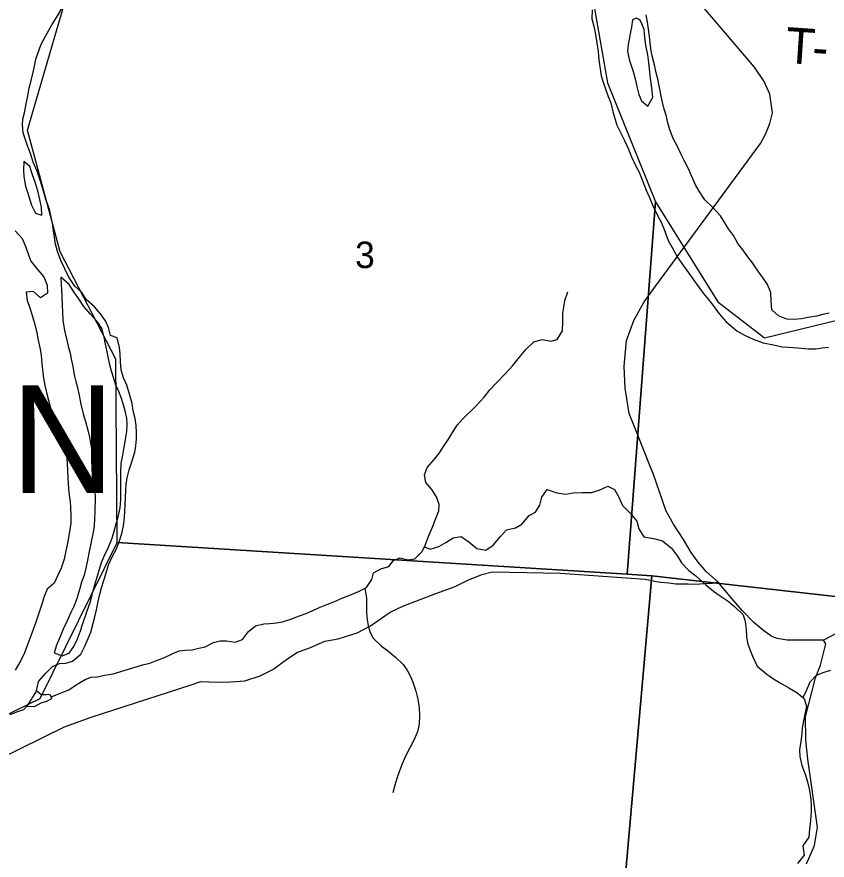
# Model space of a CAD drawing. Extents: x 0 to 34, y 0 to 22.
# Drawn here: x 26.095 to 27.377, y 16.768 to 18.103 of the extents above; entities that cross this region are included whole.
import ezdxf

# ---------------------------------------------------------------- set-up
doc = ezdxf.new("R2010")
doc.units = 0
for name, color, linetype in [('GM_X_County_Road', 7, 'Continuous'), ('GM_X_Major_River', 7, 'Continuous'), ('GM_X_Minor_River', 7, 'Continuous'), ('GM_X_Section', 7, 'Continuous'), ('GM_X_Section_Text', 7, 'Continuous'), ('GM_X_State_Route', 7, 'Continuous'), ('GM_X_Township_Road', 7, 'Continuous'), ('GM_X_Township_Road_Text', 7, 'Continuous'), ('GM_X_Township_Text', 7, 'Continuous')]:
    doc.layers.add(name, color=color, linetype=linetype)

msp = doc.modelspace()

# ---------------------------------------------------------------- linework, layer by layer
at = {"layer": 'GM_X_County_Road'}
for points in [[(26.066, 16.9284), (26.1704, 16.9793), (26.2127, 16.9945), (26.3706, 17.0458), (26.3861, 17.0514), (26.4111, 17.0501), (26.4335, 17.0507), (26.4558, 17.0521), (26.4801, 17.06), (26.4998, 17.0701), (26.5215, 17.0859), (26.5378, 17.0969), (26.5598, 17.1051), (26.5822, 17.1148), (26.6034, 17.1189), (26.6334, 17.1282), (26.6543, 17.1391), (26.6854, 17.161), (26.7059, 17.1703), (26.7332, 17.1808), (26.7579, 17.1902), (26.7882, 17.2014), (26.8084, 17.2115), (26.8304, 17.2205), (26.847, 17.225), (26.9549, 17.2225), (27.0893, 17.2131), (27.1068, 17.2096), (27.1135, 17.2083), (27.1266, 17.2073), (27.1376, 17.2058), (27.1441, 17.2058)], [(27.1441, 17.2058), (27.1462, 17.2058), (27.1572, 17.2056), (27.1676, 17.2053), (27.1757, 17.2056), (27.1888, 17.2066), (27.1952, 17.2068), (27.2039, 17.2091)]]:
    msp.add_lwpolyline(points, dxfattribs=at)
at = {"layer": 'GM_X_Major_River'}
msp.add_line((26.1259, 17.0362), (26.1106, 17.0119), dxfattribs=at)
for points in [[(26.2324, 17.2113), (26.2364, 17.2234), (26.2399, 17.2359), (26.2457, 17.2487), (26.2519, 17.26), (26.2569, 17.2725), (26.2612, 17.2853), (26.2636, 17.2978), (26.2653, 17.311), (26.2658, 17.3213), (26.2663, 17.3307), (26.2667, 17.3417), (26.2673, 17.3542), (26.2677, 17.3637), (26.2694, 17.3735), (26.2725, 17.3864), (26.2768, 17.3989), (26.2815, 17.414), (26.2831, 17.4242), (26.284, 17.4348), (26.2841, 17.445), (26.2835, 17.4564), (26.2821, 17.4674), (26.2792, 17.4796), (26.2774, 17.4914), (26.2734, 17.5058), (26.2687, 17.5203), (26.2635, 17.5317), (26.2598, 17.5443), (26.2589, 17.5579), (26.2582, 17.5701), (26.2572, 17.5799), (26.2536, 17.5951), (26.243, 17.599), (26.2401, 17.6116), (26.2353, 17.6223), (26.2275, 17.6333), (26.2178, 17.6441), (26.2047, 17.656), (26.198, 17.6667), (26.1867, 17.677), (26.1774, 17.6912), (26.1708, 17.7045), (26.1649, 17.7163), (26.1597, 17.73), (26.1561, 17.7437), (26.1543, 17.7544), (26.1529, 17.7646), (26.1511, 17.7768), (26.149, 17.7863), (26.1464, 17.7988), (26.1409, 17.814), (26.138, 17.8239), (26.1351, 17.8349), (26.1318, 17.8448), (26.127, 17.8589), (26.1208, 17.8734), (26.1164, 17.8871), (26.1116, 17.8989), (26.105, 17.9195), (26.104, 17.932), (26.1045, 17.9414), (26.1072, 17.9513), (26.1097, 17.9657), (26.1124, 17.9781), (26.1145, 17.9902), (26.1176, 18.0027), (26.1208, 18.0156), (26.1228, 18.0254), (26.1252, 18.0364), (26.1334, 18.0602), (26.1399, 18.0719), (26.1503, 18.0907), (26.1576, 18.1024), (26.1677, 18.1193)], [(27.0054, 18.1145), (27.0049, 18.1001), (27.0082, 18.0864), (27.0103, 18.0753), (27.0124, 18.0621), (27.0146, 18.0484), (27.0159, 18.0351), (27.0195, 18.01), (27.0224, 18.0001), (27.0268, 17.9876), (27.0308, 17.9773), (27.0345, 17.967), (27.0381, 17.9537), (27.041, 17.9423), (27.0443, 17.932), (27.0517, 17.9172), (27.0566, 17.9073), (27.0625, 17.8939), (27.0673, 17.8817), (27.0743, 17.8669), (27.0795, 17.8573), (27.0905, 17.8288), (27.0957, 17.8173), (27.1012, 17.804), (27.1079, 17.7899), (27.1142, 17.7781), (27.119, 17.7666), (27.1256, 17.7495), (27.1319, 17.7384), (27.1408, 17.722), (27.1498, 17.7094), (27.158, 17.6976), (27.1699, 17.6811), (27.1807, 17.6659), (27.1889, 17.6563), (27.1967, 17.6463), (27.2061, 17.633), (27.2173, 17.6207), (27.2341, 17.6061), (27.2465, 17.5992), (27.2601, 17.5929), (27.2759, 17.5874), (27.2922, 17.5839), (27.3057, 17.581), (27.3159, 17.5802)], [(27.3236, 17.6241), (27.3134, 17.6246), (27.2998, 17.63), (27.2893, 17.6396), (27.2887, 17.6537), (27.2877, 17.6669), (27.2822, 17.6806), (27.2729, 17.6933), (27.2662, 17.7028), (27.2587, 17.7139), (27.2517, 17.7235), (27.2438, 17.7345), (27.2356, 17.7445), (27.2286, 17.7571), (27.2211, 17.7678), (27.2152, 17.7773), (27.2081, 17.7884), (27.1958, 17.8018), (27.1834, 17.8137), (27.1745, 17.8271), (27.1689, 17.8374), (27.1626, 17.8518), (27.1582, 17.8618), (27.1508, 17.8759), (27.1449, 17.8873), (27.1404, 17.8983), (27.1341, 17.9098), (27.1279, 17.9243), (27.1249, 17.9357), (27.1221, 17.9478), (27.1191, 17.9574), (27.1162, 17.9703), (27.1137, 17.9805), (27.1119, 17.9916), (27.109, 18.0052), (27.1065, 18.0147), (27.1036, 18.0273), (27.1007, 18.0395), (27.0986, 18.0493), (27.0968, 18.0615), (27.0958, 18.0725), (27.0944, 18.0839), (27.0926, 18.0949), (27.0905, 18.1063)], [(27.0689, 18.0988), (27.0673, 18.087), (27.0648, 18.0738), (27.062, 18.0594), (27.0611, 18.0492), (27.064, 18.0358), (27.0699, 18.0168), (27.0731, 18.005), (27.076, 17.9932), (27.0793, 17.9806), (27.0834, 17.9703), (27.0935, 17.9619), (27.1012, 17.9762), (27.0995, 17.9907), (27.0974, 18.0055), (27.0964, 18.0161), (27.095, 18.0305), (27.0933, 18.0431), (27.09, 18.0583), (27.0883, 18.0705), (27.0873, 18.0834)], [(27.0873, 18.0834), (27.0836, 18.092), (27.0815, 18.0972), (27.0784, 18.0998), (27.0749, 18.1011), (27.0689, 18.0988)], [(26.1061, 17.8742), (26.1052, 17.8606), (26.1062, 17.8507), (26.1087, 17.8355), (26.1116, 17.826), (26.1182, 17.8054), (26.1245, 17.7924), (26.1347, 17.7893), (26.134, 17.8014), (26.1315, 17.8143), (26.1283, 17.828), (26.1239, 17.8414), (26.1198, 17.8532), (26.1155, 17.8665)], [(26.1155, 17.8665), (26.1061, 17.8742)], [(26.0924, 17.7645), (26.1036, 17.7526), (26.1091, 17.7389), (26.1131, 17.7264), (26.1172, 17.7165), (26.1276, 17.7035), (26.1377, 17.6916), (26.1429, 17.6787), (26.1435, 17.6661), (26.1325, 17.6583), (26.1212, 17.6683), (26.1095, 17.6673), (26.1112, 17.6544), (26.1156, 17.6429), (26.1197, 17.6289), (26.1233, 17.6163), (26.1266, 17.603), (26.1287, 17.5916), (26.1316, 17.5775), (26.1334, 17.5673), (26.1344, 17.5544), (26.1354, 17.5445), (26.1371, 17.5312), (26.1393, 17.5198), (26.1426, 17.5065), (26.1451, 17.4966), (26.1487, 17.4822), (26.1524, 17.4708), (26.1546, 17.4613), (26.1593, 17.448), (26.163, 17.4384), (26.1671, 17.4289), (26.1707, 17.4183), (26.1733, 17.4087)], [(26.1646, 17.6914), (26.1652, 17.68), (26.1655, 17.6705), (26.1662, 17.6606), (26.1664, 17.6466), (26.167, 17.6367), (26.1676, 17.623), (26.1705, 17.6067), (26.1737, 17.5934), (26.1763, 17.5819), (26.1792, 17.5709), (26.1813, 17.5595), (26.1835, 17.5496), (26.1856, 17.5367), (26.1885, 17.526), (26.1907, 17.5165), (26.1936, 17.5039), (26.1964, 17.4903), (26.2, 17.4747), (26.2037, 17.4628), (26.207, 17.4491), (26.2099, 17.4381), (26.2116, 17.4286), (26.2134, 17.4172), (26.2148, 17.4058), (26.2158, 17.3963), (26.2165, 17.3868), (26.2171, 17.375), (26.2181, 17.3617), (26.2183, 17.3519), (26.2186, 17.3424), (26.2184, 17.3192), (26.2179, 17.3097), (26.217, 17.2965), (26.2149, 17.2847), (26.2121, 17.2696), (26.2093, 17.2567), (26.2069, 17.2434), (26.2041, 17.2306), (26.2013, 17.2196), (26.1974, 17.2083), (26.1946, 17.1984), (26.1899, 17.1825), (26.1852, 17.1701), (26.1802, 17.1603), (26.1743, 17.1474), (26.1681, 17.1338), (26.1638, 17.1233), (26.1576, 17.1085), (26.154, 17.0964), (26.1665, 17.0917), (26.1779, 17.0962), (26.1849, 17.1067), (26.1911, 17.1188), (26.1954, 17.1316), (26.1989, 17.1415), (26.2063, 17.163), (26.2107, 17.1762), (26.2134, 17.1864), (26.2174, 17.2008), (26.2202, 17.2118), (26.2245, 17.2254), (26.2288, 17.2394), (26.2331, 17.2496), (26.2397, 17.2639), (26.2456, 17.2783), (26.2487, 17.2889), (26.2522, 17.3006), (26.2554, 17.312), (26.2582, 17.326), (26.2595, 17.3389), (26.2597, 17.3582), (26.2595, 17.3707), (26.2592, 17.3814), (26.2602, 17.3962), (26.2626, 17.4094), (26.2646, 17.4219), (26.267, 17.434), (26.2687, 17.4469), (26.2696, 17.4583), (26.2689, 17.4682), (26.2664, 17.4796), (26.2631, 17.4906), (26.2598, 17.5009), (26.2565, 17.5104), (26.2517, 17.5204), (26.2484, 17.531), (26.2448, 17.5424), (26.2419, 17.5527), (26.2401, 17.5622), (26.2372, 17.5759), (26.2354, 17.5854), (26.2329, 17.5961), (26.23, 17.609), (26.224, 17.6186), (26.2113, 17.6328), (26.2008, 17.6447), (26.193, 17.6569), (26.1863, 17.6665), (26.1777, 17.6795)], [(26.1777, 17.6795), (26.1646, 17.6914)], [(27.3804, 17.634), (27.3702, 17.6319), (27.3604, 17.6297), (27.3471, 17.6272), (27.3365, 17.6254), (27.3236, 17.6241)], [(27.3159, 17.5802), (27.3303, 17.5793), (27.3477, 17.5779), (27.3594, 17.5778), (27.3693, 17.5796), (27.3791, 17.5806)], [(26.1733, 17.4087), (26.1743, 17.397), (26.1749, 17.3848), (26.1755, 17.3731), (26.1769, 17.3568), (26.1775, 17.3461), (26.1793, 17.3359), (26.18, 17.3264), (26.1802, 17.3135), (26.1801, 17.3021), (26.1788, 17.2915), (26.1768, 17.279), (26.1744, 17.2677), (26.1724, 17.2579), (26.1696, 17.2446), (26.1649, 17.2303), (26.1603, 17.2205), (26.1541, 17.2069), (26.143, 17.1971), (26.138, 17.1858), (26.1352, 17.1752), (26.1317, 17.1654), (26.1282, 17.1545), (26.1243, 17.1435), (26.1208, 17.1337), (26.1169, 17.1235), (26.1122, 17.111), (26.1068, 17.0967), (26.101, 17.0843), (26.0921, 17.0692)], [(26.1259, 17.0362), (26.1294, 17.0513), (26.1408, 17.0645), (26.1512, 17.075), (26.1626, 17.0794), (26.1724, 17.0804), (26.183, 17.0833), (26.1964, 17.0942), (26.2026, 17.107), (26.2076, 17.1191), (26.2119, 17.1293), (26.2158, 17.1433), (26.2182, 17.1535), (26.221, 17.1644), (26.2238, 17.1777), (26.2262, 17.1894), (26.2289, 17.1996), (26.2324, 17.2113)], [(26.1106, 17.0119), (26.1231, 17.0114), (26.1334, 17.0173), (26.1422, 17.0199), (26.1502, 17.024), (26.148, 17.0297), (26.1446, 17.0305), (26.1412, 17.0302), (26.1332, 17.0299), (26.1259, 17.0362)], [(26.0842, 16.9991), (26.0963, 17.0036), (26.1058, 17.0069), (26.1106, 17.0119)]]:
    msp.add_lwpolyline(points, dxfattribs=at)
at = {"layer": 'GM_X_Minor_River'}
for points in [[(26.1491, 17.0269), (26.1773, 17.0377), (26.1906, 17.047), (26.2028, 17.0541), (26.2127, 17.0582), (26.2226, 17.0588), (26.2336, 17.061), (26.2473, 17.0635), (26.2663, 17.0693), (26.2785, 17.073), (26.2937, 17.0777), (26.3051, 17.0803), (26.3161, 17.0843), (26.3275, 17.0884), (26.3409, 17.0947), (26.3515, 17.0995), (26.3614, 17.1009), (26.3724, 17.1015), (26.383, 17.1037), (26.3929, 17.1062), (26.4062, 17.1129), (26.4165, 17.1154), (26.4267, 17.1153), (26.4404, 17.1136), (26.4518, 17.1177), (26.4614, 17.1301), (26.4725, 17.1394), (26.4858, 17.1427), (26.4953, 17.143), (26.5059, 17.144), (26.5154, 17.1454), (26.5283, 17.1498), (26.5405, 17.1546), (26.5527, 17.159), (26.563, 17.1638), (26.5748, 17.1686), (26.5854, 17.173), (26.5965, 17.1771), (26.6109, 17.1834), (26.6246, 17.1889), (26.6353, 17.1937), (26.6483, 17.2), (26.6564, 17.2128), (26.6595, 17.223), (26.671, 17.2294), (26.6835, 17.233), (26.6908, 17.2428), (26.7011, 17.2469), (26.7139, 17.244), (26.7246, 17.2451), (26.7364, 17.2567), (26.7415, 17.268), (26.747, 17.2824), (26.7524, 17.2956), (26.7567, 17.3066), (26.7626, 17.3213), (26.7631, 17.3315), (26.7587, 17.3437), (26.7516, 17.3552), (26.7419, 17.3663), (26.7397, 17.3785), (26.7444, 17.3898), (26.7555, 17.4033), (26.7636, 17.4131), (26.7702, 17.4229), (26.7779, 17.4346), (26.7844, 17.4451), (26.7918, 17.4568), (26.8002, 17.4666), (26.8205, 17.4865), (26.8343, 17.5011), (26.8432, 17.5131), (26.8536, 17.5237), (26.867, 17.5375), (26.8796, 17.5514), (26.8904, 17.5646), (26.9008, 17.577), (26.9127, 17.589), (26.926, 17.5926), (26.9396, 17.5898), (26.9498, 17.5928), (26.9583, 17.6063), (26.9589, 17.6207), (26.959, 17.634), (26.9603, 17.6435), (26.9619, 17.6541), (26.9666, 17.6681)], [(26.7398, 17.2641), (26.749, 17.2607), (26.7627, 17.2651), (26.7737, 17.2714), (26.7852, 17.2785), (26.7981, 17.2806), (26.8101, 17.2725), (26.8229, 17.2618), (26.8369, 17.2589), (26.8487, 17.2672), (26.8603, 17.2807), (26.8699, 17.2912), (26.8839, 17.2945), (26.8938, 17.3004), (26.9057, 17.3139), (26.9153, 17.3191), (26.9226, 17.3304), (26.9258, 17.3429), (26.9342, 17.355), (26.9493, 17.3499), (26.9637, 17.3478), (26.9751, 17.35), (26.9895, 17.3505), (27.0043, 17.3504), (27.0165, 17.354), (27.0302, 17.3603), (27.0407, 17.3549), (27.0467, 17.3438), (27.0533, 17.3297), (27.0653, 17.3178), (27.0758, 17.3051), (27.0791, 17.293), (27.0869, 17.2803), (27.1024, 17.2775), (27.1167, 17.2739), (27.1306, 17.2624), (27.14, 17.2494), (27.1467, 17.239), (27.1583, 17.2268), (27.1692, 17.2183), (27.1853, 17.2041), (27.1973, 17.1944), (27.2075, 17.1867), (27.2202, 17.1782), (27.2304, 17.1701), (27.2443, 17.1567), (27.2475, 17.146), (27.2489, 17.1335), (27.2492, 17.1225), (27.251, 17.1122), (27.2546, 17.1016), (27.2587, 17.0913), (27.2665, 17.0756), (27.2815, 17.0625), (27.2924, 17.0556), (27.3029, 17.049), (27.3165, 17.0409), (27.3289, 17.0339), (27.3409, 17.0243), (27.3442, 17.0117), (27.3425, 17.0019), (27.3401, 16.9913), (27.3377, 16.978), (27.3369, 16.9685), (27.3356, 16.956), (27.3335, 16.9431), (27.3338, 16.9325), (27.337, 16.9184), (27.3422, 16.9043), (27.3458, 16.8925), (27.3484, 16.8815), (27.3505, 16.8686), (27.3515, 16.8564), (27.3518, 16.8458), (27.3508, 16.831), (27.3492, 16.8181), (27.3479, 16.8045)], [(26.6457, 17.1988), (26.6481, 17.1833), (26.6479, 17.1727), (26.6482, 17.1621), (26.6489, 17.1526), (26.651, 17.1396), (26.6535, 17.1301), (26.6583, 17.1202), (26.6718, 17.1071), (26.6816, 17.1002), (26.694, 17.0898), (26.706, 17.0779), (26.7131, 17.068), (26.7183, 17.058), (26.7219, 17.0485), (26.726, 17.0356), (26.7292, 17.023), (26.7317, 17.0093), (26.732, 16.9979), (26.7314, 16.9835), (26.729, 16.9714), (26.7232, 16.9585), (26.7166, 16.9461), (26.7104, 16.934), (26.7046, 16.9208), (26.7003, 16.9095), (26.696, 16.8978), (26.6928, 16.8868), (26.6897, 16.8751)], [(27.3389, 17.0259), (27.3441, 17.0371), (27.3499, 17.0507), (27.3603, 17.0612), (27.3724, 17.0657), (27.3827, 17.0693)], [(27.3479, 16.8045), (27.3385, 16.791), (27.3405, 16.7762), (27.33, 16.7628)]]:
    msp.add_lwpolyline(points, dxfattribs=at)
at = {"layer": 'GM_X_Section'}
for points in [[(26.2918, 18.2374), (26.9928, 18.2098), (27.0297, 17.9987), (27.1053, 17.8104), (27.0604, 17.2208), (26.2538, 17.2713), (26.2518, 17.5615), (26.1636, 17.7312), (26.1119, 17.9239), (26.1712, 18.1282)], [(28.073, 18.087), (28.157, 18.0791), (28.0732, 17.1088), (27.0998, 17.2184), (27.0604, 17.2208), (27.1053, 17.8104), (27.2042, 17.652), (27.2781, 17.5952), (27.3324, 17.6084), (27.5334, 17.6576), (27.8207, 17.7804), (28.0174, 18.0299)], [(26.2538, 17.2713), (27.0604, 17.2208), (27.0998, 17.2184), (27.0114, 16.2186), (25.9802, 16.2732), (26.0152, 16.9679), (26.1318, 17.0242)], [(27.0998, 17.2184), (28.0732, 17.1088), (28.0465, 16.1852), (28.0441, 16.1595), (27.0114, 16.2186)]]:
    msp.add_lwpolyline(points, close=True, dxfattribs=at)
at = {"layer": 'GM_X_State_Route'}
for points in [[(27.0589, 17.5054), (27.0574, 17.5148), (27.0557, 17.5501), (27.0594, 17.5908), (27.0711, 17.6227), (27.0873, 17.652), (27.0987, 17.6676), (27.2718, 17.9028), (27.2801, 17.9184), (27.2862, 17.9347), (27.2903, 17.9514), (27.2864, 17.981), (27.2772, 18.0008), (27.262, 18.0239), (27.1485, 18.1572), (27.0638, 18.2546)], [(27.0976, 17.3904), (27.0765, 17.4437), (27.0639, 17.4754), (27.0589, 17.5054)], [(27.2293, 17.179), (27.2039, 17.2091), (27.1861, 17.2249), (27.1732, 17.24), (27.1621, 17.2554), (27.1496, 17.2758), (27.1339, 17.3001), (27.1225, 17.3206), (27.1015, 17.3805), (27.0976, 17.3904)], [(27.3922, 17.1276), (27.371, 17.1166), (27.355, 17.1165), (27.3387, 17.1165), (27.3137, 17.1168), (27.2977, 17.1193), (27.2896, 17.1223), (27.2771, 17.1315), (27.2612, 17.1447), (27.2425, 17.1633), (27.2293, 17.179)]]:
    msp.add_lwpolyline(points, dxfattribs=at)
at = {"layer": 'GM_X_Township_Road'}
msp.add_lwpolyline([(27.3446, 16.7624), (27.3572, 16.7917), (27.3617, 16.8205), (27.3467, 16.928), (27.3431, 16.9586), (27.3428, 16.9953), (27.3586, 17.0567), (27.3664, 17.0768), (27.375, 17.1107), (27.371, 17.1166)], dxfattribs=at)

# ---------------------------------------------------------------- texts
at = {"layer": 'GM_X_Section_Text'}
msp.add_text('3', height=0.0419, rotation=0, dxfattribs=at).set_placement((26.6301, 17.7056))
at = {"layer": 'GM_X_Township_Road_Text'}
for s, rotation, p in [('T', 356.0414, (27.3096, 18.0305)), ('-', 356.1558, (27.3521, 18.0276))]:
    msp.add_text(s, height=0.0568, rotation=rotation, dxfattribs=at).set_placement(p)
at = {"layer": 'GM_X_Township_Text'}
msp.add_text('JACKSON', height=0.17045, rotation=0, dxfattribs=at).set_placement((25.1734, 17.3493))

doc.saveas('drawing.dxf')
